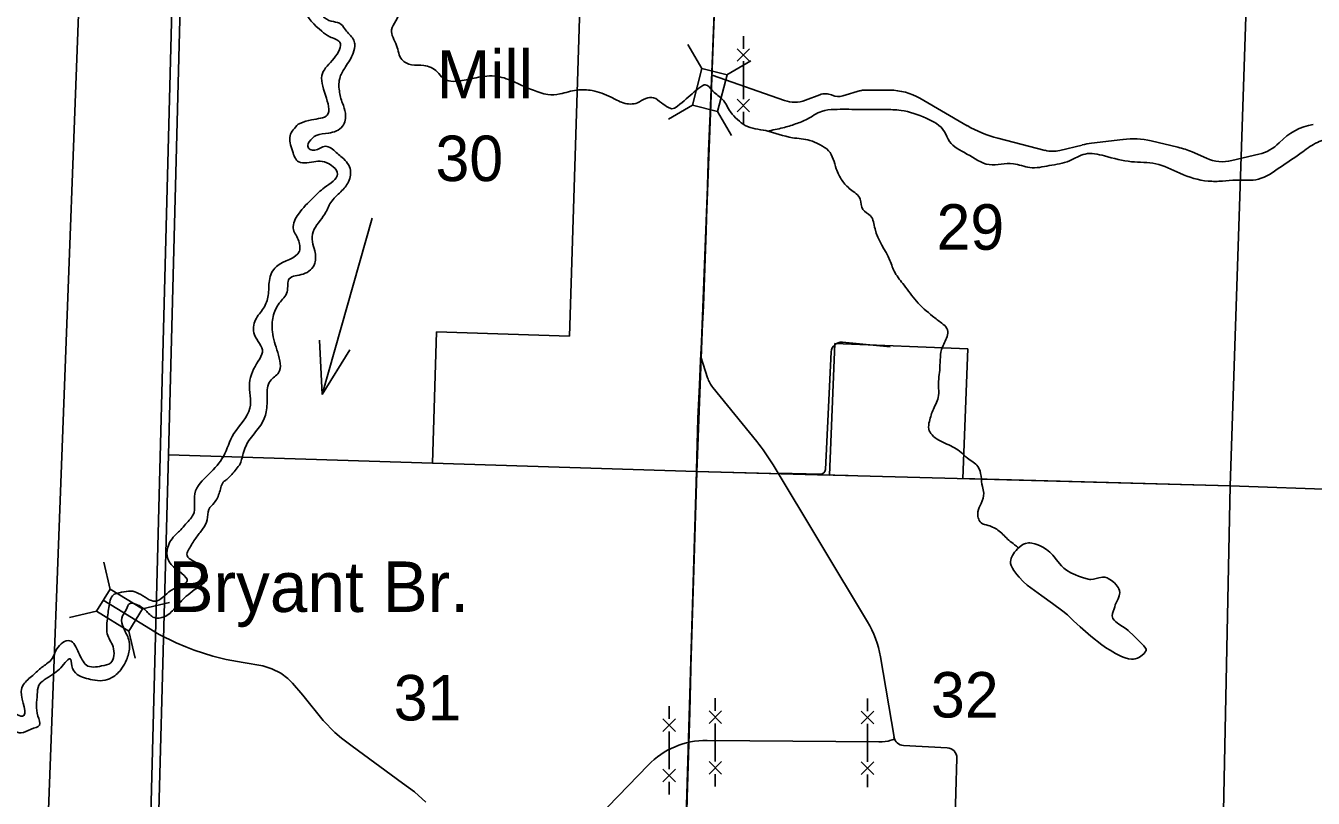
# Model space of a CAD drawing. Extents: x 1219626 to 1426462, y 456797 to 752399.
# Drawn here: x 1247072 to 1259805, y 632428 to 640071 of the extents above; entities that cross this region are included whole.
import ezdxf

# ---------------------------------------------------------------- set-up
doc = ezdxf.new("R2010")
doc.units = 0
for name, color, linetype in [('Bridges and Drawbridges Local Roads', 7, 'Continuous'), ('Communities and Subdivisions Names without Post Office', 7, 'Continuous'), ('County Boundary', 7, 'Continuous'), ('Lakes and Ponds', 7, 'Continuous'), ('Lakes and Ponds Text', 7, 'Continuous'), ('Local Roads Improved', 7, 'Continuous'), ('Local Roads Paved', 7, 'Continuous'), ('Masks', 7, 'Continuous'), ('Narrow River Creek and Branch and Slough', 7, 'Continuous'), ('Narrow River Creek and Branch and Slough Text', 7, 'Continuous'), ('Section Lines', 7, 'Continuous'), ('Section Numbers', 7, 'Continuous'), ('State Forest', 7, 'Continuous'), ('Uninventoried Roads and Features', 7, 'Continuous')]:
    doc.layers.add(name, color=color, linetype=linetype)

msp = doc.modelspace()

# ---------------------------------------------------------------- linework, layer by layer
at = {"layer": 'Bridges and Drawbridges Local Roads'}
for p, q in [((1253759, 639649), (1253620, 639886)), ((1254005, 639584), (1254242, 639724)), ((1253759, 639649), (1253665, 639286)), ((1254007, 639585), (1253759, 639649)), ((1253913, 639222), (1254007, 639585)), ((1253665, 639286), (1253428, 639147)), ((1253665, 639286), (1253913, 639222)), ((1253913, 639222), (1254053, 638985)), ((1247906, 634495), (1247843, 634763)), ((1247906, 634497), (1247772, 634279)), ((1248225, 634301), (1247906, 634497)), ((1247772, 634279), (1247504, 634216)), ((1247772, 634279), (1248091, 634083)), ((1248091, 634083), (1248225, 634301)), ((1248225, 634301), (1248493, 634364)), ((1248091, 634083), (1248155, 633815))]:
    msp.add_line(p, q, dxfattribs=at)
at = {"layer": 'County Boundary'}
msp.add_line((1248613, 643832), (1248115, 624997), dxfattribs=at)
at = {"layer": 'Lakes and Ponds'}
for p, q in [((1249767, 639096), (1249775, 639100)), ((1249088, 635608), (1249059, 635581))]:
    msp.add_line(p, q, dxfattribs=at)
msp.add_lwpolyline([(1256881, 634897), (1256866, 634880), (1256852, 634862), (1256830, 634829), (1256819, 634804), (1256813, 634784), (1256811, 634770), (1256811, 634750), (1256817, 634731), (1256830, 634705), (1256844, 634683), (1256872, 634643), (1256896, 634614), (1256935, 634573), (1256977, 634537), (1257048, 634483), (1257120, 634430), (1257225, 634355), (1257328, 634279), (1257373, 634242), (1257435, 634182), (1257499, 634123), (1257605, 634033), (1257715, 633946), (1257760, 633914), (1257795, 633892), (1257849, 633862), (1257903, 633833), (1257924, 633823), (1257944, 633816), (1257979, 633806), (1258007, 633803), (1258028, 633804), (1258043, 633806), (1258066, 633813), (1258088, 633825), (1258114, 633845), (1258132, 633862), (1258142, 633876), (1258148, 633885), (1258151, 633893), (1258151, 633903), (1258147, 633913), (1258129, 633935), (1258094, 633973), (1258034, 634031), (1257973, 634087), (1257954, 634103), (1257883, 634150), (1257850, 634176), (1257836, 634191), (1257824, 634208), (1257818, 634221), (1257817, 634233), (1257819, 634255), (1257842, 634323), (1257847, 634341), (1257875, 634401), (1257886, 634432), (1257890, 634447), (1257891, 634462), (1257889, 634483), (1257883, 634500), (1257876, 634515), (1257857, 634540), (1257840, 634558), (1257811, 634582), (1257778, 634603), (1257766, 634608), (1257743, 634614), (1257722, 634614), (1257685, 634609), (1257631, 634596), (1257604, 634593), (1257591, 634594), (1257578, 634597), (1257523, 634612), (1257483, 634626), (1257453, 634638), (1257409, 634659), (1257366, 634684), (1257337, 634706), (1257315, 634727), (1257280, 634769), (1257229, 634832), (1257200, 634863), (1257184, 634877), (1257166, 634890), (1257130, 634913), (1257103, 634927), (1257082, 634936), (1257052, 634947), (1257021, 634953), (1257003, 634955), (1256988, 634954), (1256960, 634949), (1256939, 634941), (1256924, 634933), (1256902, 634917), (1256881, 634897)], dxfattribs=at)
for points in [[(1249775, 639100), (1249791, 639107), (1249899, 639141), (1250054, 639187), (1250036, 639383), (1250006, 639600), (1250121, 639749), (1250177, 639909), (1250079, 639962), (1249999, 640017), (1249835, 640240), (1249904, 640421), (1249998, 640445), (1250125, 640373), (1250268, 640322), (1250224, 640441), (1250190, 640501), (1250092, 640578), (1250071, 640678), (1250109, 640766), (1250258, 640937), (1250360, 641131), (1250384, 641265), (1250385, 641400), (1250307, 641642), (1250315, 641805), (1250444, 642133), (1250520, 642484), (1250493, 642608), (1250443, 642771), (1250400, 643063), (1250362, 643094), (1250173, 643193), (1250119, 643254), (1250108, 643385), (1250072, 643548), (1249981, 643683), (1249955, 643857), (1249972, 643974), (1249989, 644102), (1249850, 644251), (1249770, 644337), (1249717, 644546), (1249721, 644683), (1249690, 644772), (1249524, 644740), (1249419, 644590), (1249369, 644534), (1249260, 644507), (1249189, 644533), (1249122, 644726), (1249178, 644847), (1249255, 644929), (1249292, 644998), (1249268, 645246), (1249218, 645359), (1249169, 645482), (1249112, 645707), (1249120, 645818), (1249166, 645938), (1249187, 646042), (1249127, 646126), (1249037, 646102), (1248896, 646084), (1248818, 646084), (1248664, 646166), (1248572, 646280), (1248543, 646352), (1248515, 646497), (1248582, 646575), (1248666, 646650), (1248808, 646728), (1248922, 646817), (1248916, 646898), (1248889, 646954), (1248828, 647032), (1248805, 647089), (1248805, 647177), (1248846, 647242), (1248881, 647289), (1248947, 647407), (1248953, 647534), (1248881, 647661), (1248855, 647736), (1248826, 647840), (1248857, 648023), (1248891, 648091), (1248916, 648206), (1248908, 648359), (1248902, 648472), (1248944, 648572)], [(1249595, 644912), (1249694, 644919), (1249800, 644828), (1249823, 644683), (1249838, 644577), (1249869, 644455), (1249997, 644309), (1250082, 644234), (1250135, 644150), (1250135, 644028), (1250112, 643906), (1250127, 643792), (1250211, 643616), (1250264, 643441), (1250310, 643327), (1250432, 643236), (1250523, 643129), (1250607, 643015), (1250615, 642908), (1250583, 642773), (1250616, 642647), (1250630, 642383), (1250637, 642093), (1250592, 641994), (1250539, 641895), (1250500, 641789), (1250470, 641697), (1250485, 641560), (1250531, 641431), (1250539, 641324), (1250516, 641187), (1250496, 641014), (1250447, 640898), (1250367, 640806), (1250280, 640738), (1250238, 640663), (1250287, 640562), (1250386, 640486), (1250417, 640349), (1250401, 640250), (1250333, 640227), (1250196, 640227), (1250074, 640243), (1249972, 640278), (1250027, 640150), (1250192, 640084), (1250234, 640029), (1250310, 639938), (1250325, 639891), (1250310, 639800), (1250234, 639663), (1250181, 639564), (1250173, 639427), (1250204, 639305), (1250234, 639206), (1250204, 639076), (1250067, 639008), (1249945, 638985), (1249876, 638924), (1249861, 638878), (1249884, 638848), (1249930, 638840), (1250036, 638878), (1250143, 638817), (1250188, 638779), (1250280, 638658), (1250264, 638528), (1250188, 638429), (1250089, 638322), (1250029, 638208), (1249914, 638033), (1249907, 637934), (1249930, 637843), (1249930, 637721), (1249815, 637614), (1249678, 637568), (1249656, 637439), (1249579, 637325), (1249519, 637195), (1249511, 637043), (1249564, 636837), (1249572, 636637), (1249488, 636556), (1249458, 636411), (1249450, 636251), (1249397, 636121), (1249290, 635984), (1249222, 635840), (1249184, 635725), (1249173, 635709), (1249088, 635608)], [(1245200, 632764), (1245378, 632753), (1245360, 632821), (1245280, 632947), (1245292, 633086), (1245424, 633214), (1245531, 633244), (1245707, 633288), (1245723, 633381), (1245634, 633495), (1245588, 633587), (1245576, 633678), (1245691, 633781), (1245885, 633912), (1246033, 633998), (1246199, 634028), (1246249, 634024), (1246362, 633889), (1246377, 633726), (1246335, 633598), (1246230, 633458), (1246184, 633354), (1246319, 633354), (1246521, 633272), (1246610, 633365), (1246699, 633489), (1246745, 633544), (1246855, 633575), (1246924, 633495), (1246951, 633369), (1246974, 633264), (1247040, 633241), (1247026, 633484), (1247049, 633553), (1247141, 633644), (1247232, 633724), (1247278, 633758), (1247334, 633811), (1247380, 633907), (1247506, 633987), (1247594, 633869), (1247629, 633799), (1247671, 633745), (1247822, 633737), (1247912, 633768), (1247935, 633927), (1247877, 634055), (1247873, 634137), (1247881, 634226), (1247904, 634369), (1247928, 634432), (1248020, 634466), (1248111, 634478), (1248187, 634455), (1248352, 634377), (1248512, 634486), (1248669, 634579), (1248511, 634741), (1248476, 634798), (1248476, 634912), (1248556, 635038), (1248591, 635072), (1248689, 635181), (1248727, 635232), (1248743, 635441), (1248886, 635637), (1249026, 635811), (1249130, 636036), (1249289, 636288), (1249285, 636536), (1249371, 636753), (1249413, 636843), (1249333, 637014), (1249344, 637162), (1249424, 637277), (1249470, 637402), (1249481, 637551), (1249550, 637688), (1249778, 637841), (1249767, 637955), (1249717, 638068), (1249768, 638207), (1249915, 638370), (1250027, 638471), (1250155, 638603), (1250027, 638723), (1249853, 638715), (1249772, 638723), (1249710, 638832), (1249686, 638983), (1249767, 639096)], [(1249059, 635581), (1249034, 635564), (1248989, 635458), (1248935, 635351), (1248882, 635286), (1248867, 635184), (1248821, 635092), (1248753, 635001), (1248685, 634891), (1248665, 634844), (1248782, 634744), (1248837, 634689), (1248867, 634612), (1248783, 634521), (1248623, 634392), (1248547, 634308), (1248441, 634224), (1248342, 634216), (1248258, 634285), (1248167, 634346), (1248098, 634353), (1248068, 634300), (1248022, 634209), (1248037, 634117), (1248091, 633996), (1248098, 633919), (1248068, 633798), (1248022, 633714), (1247923, 633622), (1247832, 633592), (1247733, 633600), (1247581, 633654), (1247526, 633739), (1247511, 633809), (1247461, 633770), (1247406, 633706), (1247255, 633600), (1247201, 633546), (1247185, 633455), (1247192, 633242), (1247208, 633150), (1247124, 633112), (1247025, 633074), (1246949, 633104), (1246880, 633181), (1246865, 633272), (1246865, 633363), (1246797, 633432), (1246759, 633356), (1246675, 633272), (1246599, 633188), (1246530, 633173), (1246393, 633173), (1246317, 633234), (1246211, 633234), (1246096, 633234), (1246013, 633302), (1246035, 633424), (1246119, 633539), (1246180, 633592), (1246218, 633645), (1246218, 633744), (1246172, 633820), (1246134, 633843), (1246089, 633858), (1245975, 633820), (1245860, 633752), (1245777, 633668), (1245731, 633607), (1245830, 633493), (1245868, 633455), (1245891, 633356), (1245868, 633257), (1245792, 633181), (1245739, 633135), (1245624, 633104), (1245564, 633097), (1245503, 633082), (1245465, 633021), (1245480, 632906), (1245503, 632815), (1245487, 632708), (1245442, 632632), (1245328, 632594), (1245221, 632579)]]:
    msp.add_spline(points, degree=3, dxfattribs=at)
at = {"layer": 'Lakes and Ponds Text'}
for q in [(1250498, 638166), (1249978, 636959), (1250276, 636865)]:
    msp.add_line((1250003, 636423), q, dxfattribs=at)
at = {"layer": 'Local Roads Improved'}
for p, q in [((1255148, 636940), (1255622, 636893)), ((1254980, 635681), (1255038, 636845)), ((1254513, 635643), (1254929, 635634))]:
    msp.add_line(p, q, dxfattribs=at)
msp.add_lwpolyline([(1253598, 631758), (1253614, 632431), (1253640, 633282), (1253659, 634135), (1253687, 634915), (1253705, 635675), (1253720, 636186), (1253735, 636517), (1253746, 636759), (1253776, 637301), (1253800, 638045), (1253824, 638830), (1253845, 639278), (1253888, 640362)], dxfattribs=at)
for centre, radius, start, end in [((1255138, 636840), 100, 84.3268, 177.1283), ((1254930, 635684), 50, 268.677, 357.1283)]:
    msp.add_arc(centre, radius, start, end, dxfattribs=at)
at = {"layer": 'Local Roads Paved'}
for p, q in [((1253747, 636797), (1253815, 636588)), ((1253867, 636493), (1254301, 635957)), ((1254462, 635728), (1255395, 634175)), ((1255524, 633828), (1255659, 633033)), ((1255752, 632950), (1256185, 632928)), ((1256280, 632825), (1256208, 630305))]:
    msp.add_line(p, q, dxfattribs=at)
msp.add_lwpolyline([(1251030, 632391), (1250916, 632491), (1250798, 632578), (1250299, 632944), (1250194, 633022), (1250128, 633079), (1250012, 633196), (1249812, 633448), (1249709, 633566), (1249664, 633612), (1249593, 633666), (1249507, 633709), (1249416, 633740), (1249222, 633772), (1249054, 633801), (1248923, 633834), (1248738, 633893), (1248655, 633927), (1248560, 633966), (1248392, 634048), (1247974, 634304), (1247837, 634389)], dxfattribs=at)
for centre, radius, start, end in [((1254100, 636682), 300, 198.2042, 219.0329), ((1252748, 634698), 2000, 31.0012, 39.0329), ((1254538, 633660), 1000, 9.6576, 31.0012), ((1255757, 633050), 100, 189.6576, 267.053), ((1256180, 632828), 100, 358.3686, 87.053)]:
    msp.add_arc(centre, radius, start, end, dxfattribs=at)
at = {"layer": 'Masks'}
msp.add_line((1254553, 635638), (1255204, 635621), dxfattribs=at)
msp.add_lwpolyline([(1253906, 640859), (1253710, 635653), (1253548, 630414)], dxfattribs=at)
at = {"layer": 'Narrow River Creek and Branch and Slough'}
for points in [[(1254406, 639029), (1254560, 639061), (1254684, 639099), (1254799, 639147), (1254943, 639224), (1255068, 639243), (1255297, 639243), (1255566, 639243), (1255728, 639233), (1255977, 639157), (1256159, 639023), (1256207, 638927), (1256380, 638802), (1256600, 638697), (1256839, 638706), (1257002, 638668), (1257194, 638687), (1257395, 638735), (1257548, 638802), (1257740, 638783), (1258008, 638726), (1258247, 638706), (1258487, 638611), (1258765, 638534), (1258908, 638534), (1259042, 638543), (1259263, 638553), (1259473, 638668), (1259684, 638812), (1259828, 638908), (1259981, 638956), (1260182, 638956), (1260441, 638994), (1260958, 639138), (1261284, 639233), (1261542, 639320), (1261628, 639358), (1261734, 639425), (1261849, 639511), (1262021, 639559), (1262184, 639598), (1262280, 639713), (1262385, 639866), (1262471, 639981), (1262577, 640077), (1262701, 640211), (1262701, 640336), (1262701, 640441), (1262806, 640594), (1262941, 640690), (1262960, 640776), (1262969, 640901), (1263008, 640987), (1263036, 641073), (1263151, 641131), (1263317, 641303), (1263384, 641370), (1263451, 641437), (1263489, 641437), (1263556, 641523), (1263738, 641638), (1264007, 641705), (1264275, 641715), (1264495, 641629), (1264715, 641533), (1264859, 641437), (1264974, 641332), (1265108, 641245), (1265242, 641188), (1265386, 641140), (1265482, 641073), (1265510, 641054), (1265577, 641015), (1265644, 640900), (1265750, 640747), (1265884, 640651), (1265989, 640555), (1266209, 640316), (1266315, 640182), (1266439, 639971), (1266525, 639837), (1266640, 639798), (1266727, 639750), (1266995, 639406), (1267119, 639252), (1267148, 639118), (1267158, 639022), (1267330, 638888), (1267512, 638763), (1267694, 638639), (1267838, 638572)], [(1250411, 640407), (1250465, 640458), (1250516, 640515), (1250574, 640547), (1250638, 640566), (1250695, 640579), (1250765, 640528), (1250823, 640445), (1250835, 640394), (1250835, 640368), (1250791, 640253), (1250733, 640119), (1250689, 640030), (1250740, 639876), (1250791, 639736), (1250887, 639685), (1251008, 639678), (1251142, 639614), (1251199, 639550), (1251365, 639525), (1251525, 639557), (1251736, 639570), (1251908, 639512), (1252157, 639410), (1252234, 639391), (1252355, 639397), (1252521, 639435), (1252674, 639429), (1252860, 639365), (1252981, 639308), (1253121, 639308), (1253204, 639352), (1253281, 639359), (1253358, 639308), (1253428, 639263), (1253460, 639250), (1253517, 639276), (1253683, 639416), (1253747, 639467), (1253792, 639487), (1253868, 639423), (1253964, 639340), (1254041, 639218), (1254111, 639142), (1254188, 639084), (1254392, 639033), (1254654, 638963), (1254826, 638937), (1254928, 638892), (1255011, 638835), (1255088, 638656), (1255145, 638541), (1255228, 638452), (1255324, 638356), (1255350, 638254), (1255426, 638190), (1255471, 638062), (1255618, 637749), (1255669, 637627), (1255758, 637506), (1255880, 637346), (1256041, 637198), (1256131, 637128), (1256182, 637077), (1256188, 637013), (1256137, 636891), (1256112, 636687), (1256099, 636508), (1256099, 636412), (1256048, 636278), (1256009, 636157), (1256003, 636080), (1256035, 636023), (1256182, 635933), (1256322, 635850), (1256386, 635793), (1256488, 635710), (1256520, 635614), (1256533, 635512), (1256546, 635448), (1256520, 635345), (1256488, 635262), (1256520, 635154), (1256590, 635128), (1256699, 635071), (1256795, 634981), (1256852, 634937), (1256890, 634905)]]:
    msp.add_spline(points, degree=3, dxfattribs=at)
at = {"layer": 'Section Lines'}
for p, q in [((1253906, 640860), (1253706, 635661)), ((1258983, 635519), (1259154, 640641)), ((1248482, 635825), (1253706, 635661)), ((1253706, 635661), (1253549, 630414)), ((1253706, 635661), (1258983, 635519)), ((1258873, 630196), (1258983, 635519)), ((1258983, 635519), (1264365, 635321))]:
    msp.add_line(p, q, dxfattribs=at)
msp.add_lwpolyline([(1250131, 677591), (1249920, 672310), (1249708, 667131), (1249476, 661883), (1249160, 656650), (1248972, 651482), (1248775, 646221), (1248620, 641022), (1248482, 635825), (1248341, 630602), (1248116, 624997), (1247895, 619739), (1247700, 614477), (1247450, 609188), (1247248, 603902), (1247044, 598549), (1246617, 598576), (1246398, 593766), (1246285, 588497), (1246104, 583238), (1245940, 577918), (1245647, 572677)], dxfattribs=at)
at = {"layer": 'State Forest'}
for p, q in [((1248906, 675015), (1247235, 630641)), ((1252450, 637001), (1252572, 640901)), ((1253906, 640860), (1253706, 635661)), ((1251094, 635743), (1251135, 637042)), ((1251135, 637042), (1252450, 637001)), ((1255022, 635626), (1255072, 636926)), ((1255072, 636926), (1256388, 636875)), ((1256388, 636875), (1256338, 635591)), ((1253706, 635661), (1251094, 635743)), ((1253549, 630414), (1253706, 635661)), ((1253706, 635661), (1255022, 635626)), ((1256338, 635591), (1258983, 635519)), ((1258983, 635519), (1261674, 635420))]:
    msp.add_line(p, q, dxfattribs=at)
at = {"layer": 'Uninventoried Roads and Features'}
for p, q in [((1254169, 639969), (1254169, 639844)), ((1254231, 639844), (1254106, 639719)), ((1254231, 639719), (1254106, 639844)), ((1254169, 639719), (1254169, 639344)), ((1254575, 639331), (1253861, 639583)), ((1254231, 639344), (1254106, 639219)), ((1254231, 639219), (1254106, 639344)), ((1254925, 639389), (1254783, 639334)), ((1255047, 639383), (1255041, 639386)), ((1255327, 639429), (1255152, 639376)), ((1255617, 639434), (1255371, 639435)), ((1256382, 639082), (1255914, 639353)), ((1254169, 639219), (1254169, 639094)), ((1257152, 638838), (1256684, 638959)), ((1257519, 638891), (1257298, 638837)), ((1257923, 638946), (1257612, 638908)), ((1258467, 638869), (1258201, 638931)), ((1259471, 638917), (1259467, 638913)), ((1258748, 638760), (1258606, 638822)), ((1259268, 638799), (1259000, 638737)), ((1253891, 633293), (1253891, 633418)), ((1255397, 633289), (1255397, 633414)), ((1253434, 633215), (1253434, 633340)), ((1253829, 633168), (1253954, 633293)), ((1253829, 633293), (1253954, 633168)), ((1255334, 633164), (1255459, 633289)), ((1255334, 633289), (1255459, 633164)), ((1253372, 633090), (1253497, 633215)), ((1253372, 633215), (1253497, 633090)), ((1253891, 632793), (1253891, 633168)), ((1255397, 632789), (1255397, 633164)), ((1253434, 632715), (1253434, 633090)), ((1255510, 632985), (1253809, 633000)), ((1255665, 633012), (1255629, 633002)), ((1253226, 632756), (1252310, 631808)), ((1253829, 632668), (1253954, 632793)), ((1253829, 632793), (1253954, 632668)), ((1255334, 632664), (1255459, 632789)), ((1255334, 632789), (1255459, 632664)), ((1253372, 632590), (1253497, 632715)), ((1253372, 632715), (1253497, 632590)), ((1253891, 632543), (1253891, 632668)), ((1255397, 632539), (1255397, 632664)), ((1253434, 632465), (1253434, 632590))]:
    msp.add_line(p, q, dxfattribs=at)
for centre, radius, start, end in [((1254979, 639249), 150, 65.8187, 110.9964), ((1255109, 639520), 150, 245.8187, 286.7096), ((1255370, 639285), 150, 89.7237, 106.7096), ((1255614, 638834), 600, 59.9357, 89.7237), ((1254675, 639614), 300, 250.5917, 290.9964), ((1259906, 638503), 600, 99.6538, 136.4437), ((1256983, 640121), 1200, 239.9357, 255.5721), ((1257227, 639129), 300, 255.5721, 283.6881), ((1257709, 638114), 800, 96.9337, 103.6881), ((1258020, 638152), 800, 76.8681, 96.9337), ((1258285, 638090), 800, 66.2916, 76.8681), ((1259177, 639189), 400, 283.0541, 316.4437), ((1258909, 639126), 400, 246.2916, 283.0541), ((1253802, 632200), 800, 89.4712, 135.9935), ((1255514, 633385), 400, 269.4712, 286.6823)]:
    msp.add_arc(centre, radius, start, end, dxfattribs=at)

# ---------------------------------------------------------------- texts
at = {"layer": 'Communities and Subdivisions Names without Post Office'}
msp.add_text('Mill', height=475, rotation=360, dxfattribs=at).set_placement((1251136, 639353))
at = {"layer": 'Narrow River Creek and Branch and Slough Text'}
msp.add_text('Bryant Br.', height=500, dxfattribs=at).set_placement((1248483, 634271))
at = {"layer": 'Section Numbers'}
for s, p in [('30', (1251124, 638534)), ('29', (1256079, 637855)), ('31', (1250711, 633198)), ('32', (1256024, 633227))]:
    msp.add_text(s, height=450, dxfattribs=at).set_placement(p)

doc.saveas('drawing.dxf')
